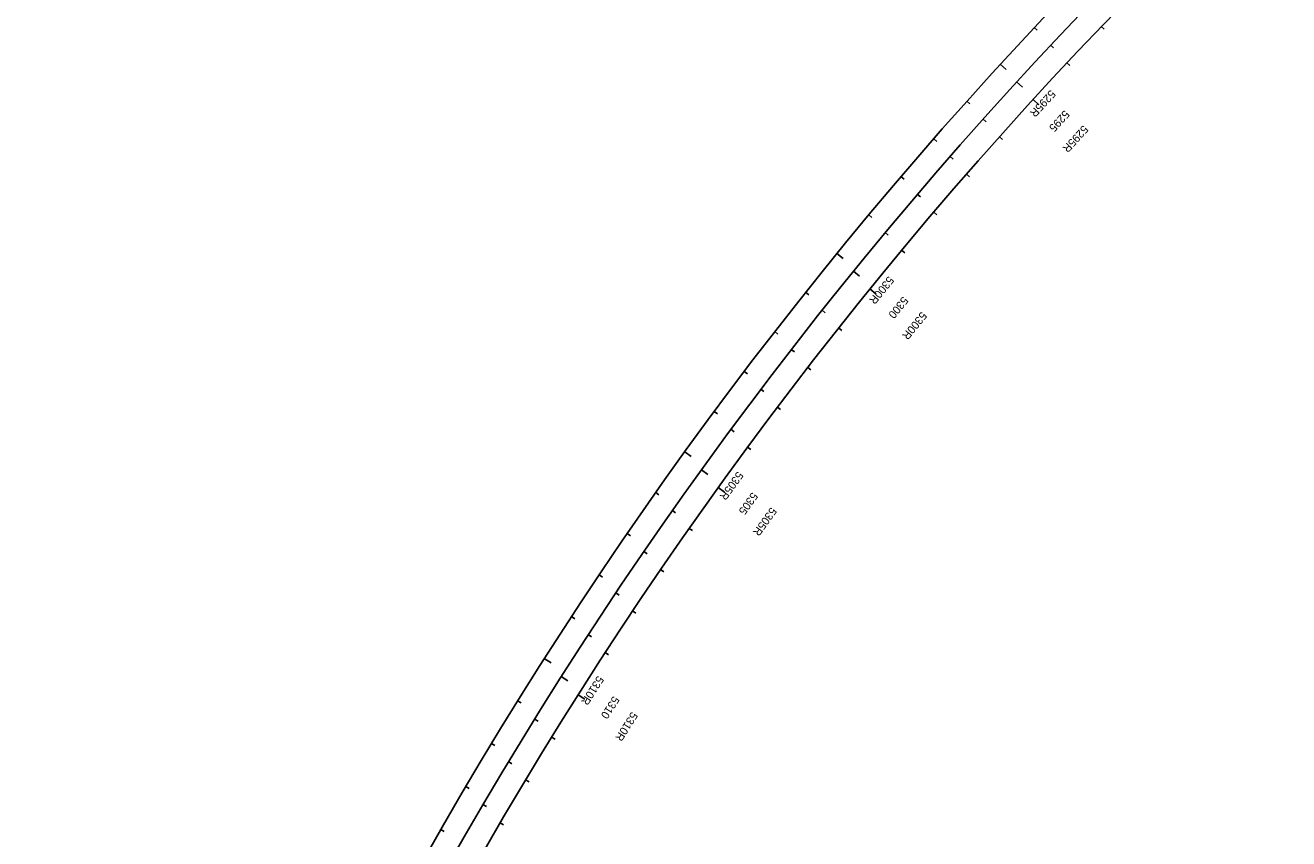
# Model space of a CAD drawing. Extents: x 2160876 to 2175625, y 601634 to 617693.
# Drawn here: x 2161211 to 2163737, y 603831 to 605458 of the extents above; entities that cross this region are included whole.
import ezdxf

# ---------------------------------------------------------------- set-up
doc = ezdxf.new("R2010")
doc.units = 0
for name, color, linetype in [('RD_HC_Cl', 7, 'Continuous'), ('RD_HC_CL_Rel', 7, 'Continuous'), ('RD_HC_Data_Tic', 7, 'Continuous'), ('RD_HC_Data_Tic_Rel', 7, 'Continuous'), ('RD_HC_TX_Rel_Sta50', 7, 'Continuous'), ('RD_HC_TX_Sta50', 7, 'Continuous')]:
    doc.layers.add(name, color=color, linetype=linetype)

msp = doc.modelspace()

# ---------------------------------------------------------------- linework, layer by layer
at = {"layer": 'RD_HC_Cl'}
msp.add_arc((2169535, 599544.7), 8593.9, 132.71947, 164.41949, dxfattribs=at)
at = {"layer": 'RD_HC_CL_Rel'}
for radius in [8641.9, 8545.9]:
    msp.add_arc((2169535, 599544.7), radius, 132.71947, 164.41949, dxfattribs=at)
at = {"layer": 'RD_HC_Data_Tic'}
for p, q in [((2163261.1, 605417.9), (2163267, 605412.4)), ((2163193.2, 605344.5), (2163205, 605333.7)), ((2163126.2, 605270.3), (2163132.1, 605265)), ((2163060, 605195.4), (2163066, 605190.1)), ((2162994.7, 605119.6), (2163000.8, 605114.4)), ((2162930.2, 605043.2), (2162936.4, 605038)), ((2162866.7, 604965.9), (2162879.1, 604955.8)), ((2162804.1, 604888), (2162810.3, 604883)), ((2162742.4, 604809.3), (2162748.7, 604804.4)), ((2162681.6, 604729.9), (2162687.9, 604725.1)), ((2162621.7, 604649.8), (2162628.1, 604645)), ((2162562.8, 604569), (2162575.7, 604559.7)), ((2162504.8, 604487.5), (2162511.3, 604482.9)), ((2162447.7, 604405.4), (2162454.3, 604400.9)), ((2162391.7, 604322.6), (2162398.3, 604318.2)), ((2162336.5, 604239.2), (2162343.2, 604234.8)), ((2162282.4, 604155.1), (2162295.9, 604146.5)), ((2162229.3, 604070.4), (2162236.1, 604066.2)), ((2162177.1, 603985.1), (2162183.9, 603980.9)), ((2162125.9, 603899.2), (2162132.8, 603895.1))]:
    msp.add_line(p, q, dxfattribs=at)
at = {"layer": 'RD_HC_Data_Tic_Rel'}
for p, q in [((2163228.5, 605453.3), (2163234.4, 605447.9)), ((2163362.6, 605455.2), (2163368.4, 605449.7)), ((2163293.9, 605382.6), (2163299.7, 605377.2)), ((2163160.6, 605380), (2163172.4, 605369.2)), ((2163093.5, 605305.8), (2163099.5, 605300.5)), ((2163226, 605309.2), (2163237.8, 605298.4)), ((2163027.3, 605230.9), (2163033.3, 605225.6)), ((2163159, 605235), (2163164.9, 605229.6)), ((2162961.9, 605155.2), (2162968, 605150)), ((2163092.8, 605160), (2163098.8, 605154.7)), ((2162897.4, 605078.8), (2162903.6, 605073.6)), ((2163027.5, 605084.2), (2163033.6, 605079)), ((2162833.8, 605001.6), (2162846.2, 604991.5)), ((2162963.2, 605007.7), (2162969.3, 605002.6)), ((2162899.7, 604930.4), (2162912.1, 604920.3)), ((2162771.1, 604923.7), (2162777.4, 604918.7)), ((2162837.1, 604852.4), (2162843.4, 604847.4)), ((2162709.4, 604845.1), (2162715.7, 604840.2)), ((2162648.5, 604765.7), (2162654.9, 604760.9)), ((2162775.5, 604773.7), (2162781.8, 604768.8)), ((2162588.5, 604685.7), (2162595, 604680.9)), ((2162714.8, 604694.2), (2162721.1, 604689.4)), ((2162529.5, 604605), (2162542.5, 604595.6)), ((2162655, 604614.1), (2162661.4, 604609.3)), ((2162471.4, 604523.6), (2162478, 604519)), ((2162596.1, 604533.2), (2162609.1, 604523.9)), ((2162538.2, 604451.7), (2162544.8, 604447.1)), ((2162414.3, 604441.5), (2162420.9, 604437)), ((2162358.1, 604358.8), (2162364.7, 604354.3)), ((2162481.3, 604369.5), (2162487.9, 604364.9)), ((2162302.9, 604275.4), (2162309.6, 604271)), ((2162425.3, 604286.6), (2162432, 604282.2)), ((2162370.3, 604203.1), (2162377, 604198.7)), ((2162248.6, 604191.4), (2162262.1, 604182.8)), ((2162316.3, 604118.9), (2162329.8, 604110.4)), ((2162195.3, 604106.8), (2162202.1, 604102.6)), ((2162143, 604021.5), (2162149.9, 604017.4)), ((2162263.3, 604034.1), (2162270.1, 604029.9)), ((2162211.2, 603948.7), (2162218.1, 603944.6)), ((2162091.7, 603935.7), (2162098.6, 603931.6)), ((2162041.4, 603849.3), (2162048.4, 603845.3)), ((2162160.2, 603862.8), (2162167.1, 603858.7))]:
    msp.add_line(p, q, dxfattribs=at)

# ---------------------------------------------------------------- texts
at = {"layer": 'RD_HC_TX_Rel_Sta50'}
for s, rotation, p in [('5295R', 227.5286, (2163261, 605329.7)), ('5295R', 227.5826, (2163326.4, 605259)), ('5300R', 230.8435, (2162937, 604957.2)), ('5300R', 230.9348, (2163002.9, 604886.2)), ('5305R', 234.1585, (2162635.1, 604566.7)), ('5305R', 234.287, (2162701.8, 604495.1)), ('5310R', 237.4735, (2162355.4, 604158)), ('5310R', 237.6393, (2162423.2, 604085.9))]:
    msp.add_text(s, height=16, rotation=rotation, dxfattribs=at).set_placement(p)
at = {"layer": 'RD_HC_TX_Sta50'}
for s, rotation, p in [('5295', 227.556, (2163288.9, 605289.1)), ('5300', 230.8895, (2162965.7, 604916.6)), ('5305', 234.223, (2162664.2, 604525.1)), ('5310', 237.5565, (2162386.5, 604117.5))]:
    msp.add_text(s, height=16, rotation=rotation, dxfattribs=at).set_placement(p)

doc.saveas('drawing.dxf')
